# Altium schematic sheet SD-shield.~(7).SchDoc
size A; SheetNumber: 1; SheetTotal: 1
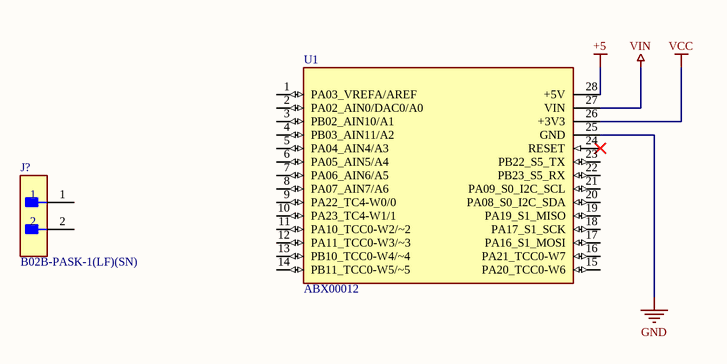
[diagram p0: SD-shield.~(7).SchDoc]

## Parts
J?  B02B-PASK-1(LF)(SN)  [FP-B02B-PASK-1_LF_SN-MFG]
U1  ABX00012  [ARDUINO_ABX00012]

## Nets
+5: U1.28(+5V)
GND: U1.25(GND)
VCC: U1.26(+3V3)
VIN: U1.27(VIN)

Not connected (* = marked no-connect by the designer): J? 1 2; U1 1(PA03_VREFA/AREF) 2(PA02_AIN0/DAC0/A0) 3(PB02_AIN10/A1) 4(PB03_AIN11/A2) 5(PA04_AIN4/A3) 6(PA05_AIN5/A4) 7(PA06_AIN6/A5) 8(PA07_AIN7/A6) 9(PA22_TC4-W0/0) 10(PA23_TC4-W1/1) 11(PA10_TCC0-W2/~2) 12(PA11_TCC0-W3/~3) 13(PB10_TCC0-W4/~4) 14(PB11_TCC0-W5/~5) 15(PA20_TCC0-W6) 16(PA21_TCC0-W7) 17(PA16_S1_MOSI) 18(PA17_S1_SCK) 19(PA19_S1_MISO) 20(PA08_S0_I2C_SDA) 21(PA09_S0_I2C_SCL) 22(PB23_S5_RX) 23(PB22_S5_TX) 24(RESET)*

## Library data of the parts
J? = CMP-17439-000415-1: CONN HEADER VERT 2POS 2MM; Number of Contacts: 2; Current Rating: 3A; Insulation Resistance: 1GR; Mated Stacking Heights: 14.9mm; Voltage Rating: 250V; Gender: Male
U1 = ABX00012: MKR footprint/pins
